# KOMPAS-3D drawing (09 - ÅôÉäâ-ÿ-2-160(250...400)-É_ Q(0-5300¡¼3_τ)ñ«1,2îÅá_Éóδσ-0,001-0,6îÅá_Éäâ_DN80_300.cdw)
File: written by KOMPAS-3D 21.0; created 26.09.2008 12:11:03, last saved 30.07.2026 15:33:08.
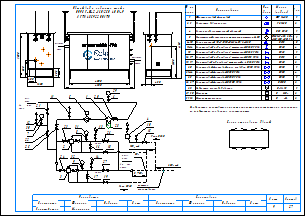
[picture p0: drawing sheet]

Sheets 1-2: A3, landscape

Document properties: Наименование: Макро:21; Автор: RaskoAdmin; Форматы листов документа: 2xA3; Полное имя файла: \\ur38nt01\Departments\КТО\КБ ПУРДГ\Заявки\Прайс-лист на типовые шкафы ГРПШ\ПУРДГ_стандарт_30_04_2026\ПУРДГ с РДГ(Н, В)\ПУРДГ-Ш-2-160(250...400)-Р_ Q(0-5300нм3_ч)до1,2МПа_Рвых-0,001-0,6МПа_РДГ_DN80_300.cdw

Title block, sheet 1: Наименование: Пункт учета газа / ПУГ-Ш-400-Р / ЛГТИ.485922.001ТУ; designation: ЛГТИ.03.4411141; sheet number: 1; Количество листов документа: 2; organisation: ООО "ЭЛЬСТЕР Газэлектроника"; Форматы листов документа: A3; stored path: C:\Рабочие документы\Компас\ПУГ\Схема.cdw; Разработал: Устинов; Проверил: Кошкин; Утвердил: Кошкин
Title block, sheet 2: sheet number: 2; stored path: D:\Рабочие документы\Заявки\ПУРДГ\ПУРДГ-ШУЭО-2-100-Р 4411220.cdw; designation, second copy: ЛГТИ.03.4411141-

Views: Вид 1, Вид 2
Referenced files: wcvoit.frw
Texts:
  Normal
  № на
  схеме
  Усл.
  обозн.
  Марка
  (модель)
  Кол.
  Фильтр газовый фланцевый
  ФГ 16-80
  Регулятор давления газа
  РДГ-50
  Клапан предохранительный сбросной
  ПСК DN25
  Измерительный комплекс с ротационным счетчиком Ду50
  СГ-ЭК-Р-(0,2...2,0)-
  Кран кнопочный VE-РАСКО-НЗ-1,6-G1/2-М20
  DN15
  Кран шаровой "под приварку" штуцерный DN20 PN16
  Кран шаровой "под приварку" штуцерный DN25 PN16
  DN20
  DN25
  Кран шаровой "под приварку" штуцерный DN15 PN16
  Кран шаровой "под приварку" штуцерный п/п DN20 PN16
  Кран шаровой фланцевый с мех. приводом DN80 PN16
  Кран шаровой фланцевый DN50 PN16
  Кран шаровой фланцевый DN80 PN16
  Кран шаровой фланцевый DN300 PN16
  DN80
  DN50
  DN300
  Индикатор перепада давления
  Манометр
  Манометр-напоромер
  Delta 15
  0...     МПа
  0...     кПа
  Общий вид и габариты шкафа
  ПУРДГ-Ш-2-160(250...400)-Р
  Выход газа
  Вход газа
  logo-rasko-ge.png
  DN 1
  местное
  сопротивление
  Римп DN20
  Выход
  газа
  Р=     кПа
  Вход
  Р=       МПа
  PDI
  Схема открывания дверей
  Предприятие изготовитель может заменять комплектующие на аналогичные,
  не ухудшающие заявленных характеристик.
  Должность
  Конструктор
  Фамилия
  Подпись
  Дата
  Согласовано
  Максимкин
  Лист
  Листов
  POLYLINE_STYLE_0.18_RGB_0_0_0
  POLYLINE_STYLE_0.50_RGB_0_0_0
  POLYLINE_STYLE_0.34_RGB_0_0_0
  PHANTOM_RGB_0_0_0_SC_1_THICK_0.18
  K5LT_THIN_RGB_0_0_0_THICK_0.18
  K5LT32769_RGB_0_0_0_THICK_0.18
  K5LT12_RGB_0_0_0_SC_1_THICK_0.18
  K5LT_DASHED_RGB_0_0_0_SC_1_THICK_0.18
  ACISOTGL_RGB_0_0_0_SC_0.8_THICK_0.25
  CONTINUOUS_RGB_0_127_31_THICK_0.3
  CONTINUOUS_RGB_0_0_255_THICK_0.35
  CONTINUOUS_RGB_255_0_0_THICK_0.35
  POLYLINE_STYLE_0.25_RGB_0_0_0
  CONTINUOUS_RGB_0_0_0_THICK_0.5
  POLYLINE_STYLE_0.35_RGB_0_0_255
  CONTINUOUS_RGB_0_0_0_THICK_0.4
  CONTINUOUS_RGB_0_0_0_THICK_0.35
  НЕВИДИМАЯ_RGB_0_0_0_SC_0.3_THICK_0.25
  СONTINUOUS_RGB_0_0_0_THICK_0.25
  ОСЕВАЯ2_RGB_248_153_30_SC_0.3_THICK_0.25
  Без оформления
Dimensions and other numbers on the sheet: 1; 2, 3; 2; 4; 5; -160 (250; 400)/1,6; 6-10; 11-14; 15; 16, 17; 18, 19; 20; 21-24; 25; 26, 27; 28; 29, 30; 31, 32; 1500; 450; 600; 1200; 550; 305; 4000; 4130; 2000; 4300; 5,,,7DN 1; 7; 30; 12; 21; 22; 11; 6; 29; 23; 31; 8; 13; 26; 18; 10; 24; 32; 9; 3; 14; 27; 19; 16; 17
